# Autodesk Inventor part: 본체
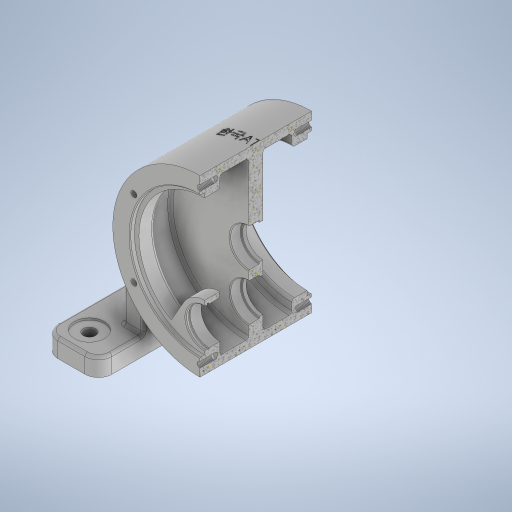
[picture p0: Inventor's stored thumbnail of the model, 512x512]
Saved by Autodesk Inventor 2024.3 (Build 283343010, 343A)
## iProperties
Created: 2025-12
Part Number: 본체
Material: 일반
Document SubType Name: Modeling
Designer: PC2-15
Density: 1 g/cm^3
Appearance: 기본값
Author: PC2-15
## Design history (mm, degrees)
sketch "스케치2"
  geometry: L1 (-135, 100)-(-75, 100); L2 (-75, 100)-(-75, -100); L3 (-75, -100)-(-135, -100); L4 (-135, -100)-(-135, 100); L5 (75, 100)-(135, 100); L6 (135, 100)-(135, -100); L7 (135, -100)-(75, -100); L8 (75, -100)-(75, 100); 2 further points
  constraints: 16 end point, 4 parallel, 2 equal length, 2 horizontal, 2 perpendicular, 1 horizontal alignment, 1 midpoint, 1 point on line
  dimensions: "d4" = 270 distance between parallel lines of L6 L4; "d5" = 135 distance from line of L4 point (0, 0) (= 0.5 x d4); "d6" = 60 distance of L5.start L5.end; "d7" = 200 distance of L5.end L6.end
extrude "돌출2" new body sketch "스케치2" distance "d8" = 20; taper "d9" = 0 deg
sketch "스케치3"
  geometry: L1 (-135, 0)-(-75, 0) reference; C1 r 97 at (0, 120); 1 further point
  constraints: 1 centre point, 1 vertical alignment
  dimensions: "d10" = 120 distance from line of L1 C1.centre; "d11" = 194 diameter of C1
extrude "돌출3" join sketch "스케치3" stored distance "d12" = 124; taper "d13" = 0 deg
sketch "스케치4"
  geometry: L1 (75, 20)-(135, 20) reference; L2 (-135, 20)-(-75, 20) reference; L3 (97, 20)-(97, 120); L4 (-97, 20)-(-97, 120); L5 (97, 120)-(75, 120); L6 (75, 120)-(75, 20); L7 (97, 20)-(75, 20); L8 (-97, 20)-(-75, 20); L9 (-75, 0)-(-75, 20) reference; L10 (-75, 20)-(-75, 120); L11 (-75, 120)-(-97, 120); A1 r 97 centre (0, 120) between (97, 120) and (-97, 120) reference; 2 further points
  constraints: 16 end point, 3 perpendicular, 3 vertical, 2 point on circle, 2 point on line, 2 tangent, 1 collinear, 1 horizontal
extrude "돌출4" join sketch "스케치4" stored distance "d14" = 100; taper "d15" = 0 deg
sketch "스케치5"
  geometry: L1 (75, 58.486)-(75, 20) reference; L2 (75, 8)-(3.735, 49.145); L3 (75, 0)-(135, 0) reference; L4 (75, 0)-(75, 20) reference; 1 further point
  constraints: 2 end point, 1 point on line
  dimensions: "d16" = 8 distance of L3.start L2.start; "d17" = 60 deg angle of L1 L2
feature "리브1" sketch "스케치5" dims "d18" = 1, "d19" = 12, "d20" = 0, "d21" = 0, "d22" = 1, "d23" = 1
sketch "스케치6"
  geometry: L1 (-62, 198)-(-57, 198); L2 (-57, 198)-(-57, 193); L3 (-57, 193)-(-40, 193); L4 (-40, 193)-(-40, 207); L5 (-40, 207)-(-8, 207); L6 (-8, 207)-(-8, 120); L7 (-8, 120)-(-62, 120); L8 (-62, 120)-(-62, 198); L9 (-62, 217)-(-62, 23) reference; L10 (62, 23)-(62, 217) reference; 3 further points
  constraints: 16 end point, 7 perpendicular, 3 midpoint, 1 horizontal
  dimensions: "d24" = 5 distance from line of L8 point (-57, 195.5); "d25" = 22 distance between parallel lines of L4 L8; "d26" = 32 distance from line of L6 point (-40, 200); "d27" = 156 diameter of L1 L7; "d28" = 146 diameter of L3 L7; "d29" = 174 diameter of L5 L7
revolve "회전1" sketch "스케치6" stored, may be unused: angle "d30" = 90 deg
sketch "스케치7"
  geometry: C1 r 87 at (0, 0) reference; 2 further points
  constraints: 1 coincident
hole "구멍1" sketch "스케치7" at (0, 0) diameter "d31" = 38; stored, may be unused: countersink angle "d35" = 90 deg, drill point angle "d37" = 118 deg; dims "d32" = 6, "d33" = 42, "d34" = 12, "d36" = 9
sketch "스케치8"
  geometry: L1 (-37.148, -62.842)-(-23.383, -39); L2 (23.383, -39)-(37.148, -62.842); L3 (0, -52.5)-(0, 0); A1 r 27 centre (0, -52.5) between (23.383, -39) and (-23.383, -39); A2 r 73 centre (0, 0) between (37.148, -62.842) and (-37.148, -62.842) reference; 1 further point
  constraints: 6 end point, 4 point on circle, 2 tangent, 1 centre point, 1 vertical, 1 vertical alignment
  dimensions: "d38" = 60 deg angle of L1 L2; "d39" = 30 deg angle of L3 L1; "d40" = 52.5 distance of L3.start L3.end; "d41" = 27 radius of A1
extrude "돌출5" join sketch "스케치8" distance "d42" = 17; taper "d43" = 0 deg
sketch "스케치9"
  geometry: L1 (-57, 88.5)-(-53.95, 88.5); L2 (-53.95, 88.5)-(-53.95, 89.75); L3 (-53.95, 89.75)-(-52, 89.75); L4 (-52, 89.75)-(-52, 88.5); L5 (-52, 88.5)-(-40, 88.5); L6 (-40, 88.5)-(-40, 67.5); L7 (-40, 67.5)-(-57, 67.5); L8 (-57, 67.5)-(-57, 88.5); L9 (-57, 94.5)-(-57, 81) reference; L10 (-57, 81)-(-57, 57.158) reference; L11 (-57, 42)-(-57, 198) reference; L12 (-57, 57.158)-(-57, 57.158) reference; L13 (-57, 57.158)-(-57, 81) reference; L14 (-57, 81)-(-57, 81) reference; L15 (-57, 81)-(-57, 57.158) reference; L16 (-50, 58.486)-(-6, 58.486) reference; L17 (-57, 81)-(-57, 81) reference; L18 (-57, 81)-(-40, 81) reference; L19 (-40, 81)-(-40, 81) reference; L20 (-57, 81)-(-40, 81) reference; L21 (-40, 57.158)-(-40, 57.158) reference; L22 (-40, 57.158)-(-40, 81) reference; L23 (-40, 81)-(-40, 81) reference; L24 (-40, 81)-(-40, 57.158) reference; L25 (-40, 33)-(-40, 207) reference; L26 (4, 99)-(-8, 99) reference; L27 (-8, 99)-(-8, 141) reference; L28 (4, 141)-(4, 99) reference; 2 further points
  constraints: 16 end point, 6 perpendicular, 4 point on line, 1 horizontal, 1 midpoint
  dimensions: "d44" = 44.5 diameter of L3 L7; "d45" = 1.95 distance between parallel lines of L2 L4; "d46" = 12 distance between parallel lines of L6 L4; "d47" = 42 diameter of L1 L7; "d108" = 52.5 distance from line of point (-8, 120) L7
revolve "회전2" sketch "스케치9" stored, may be unused: angle "d48" = 90 deg
sketch "스케치10"
  geometry: C1 r 21 at (0, -52.5) reference; 2 further points
  constraints: 1 coincident
hole "구멍2" sketch "스케치10" at (0, -52.5) diameter "d49" = 38; stored, may be unused: countersink angle "d53" = 90 deg, drill point angle "d55" = 118 deg; dims "d50" = 6, "d51" = 42, "d52" = 12, "d54" = 8
sketch "스케치11" dims "d56" = 170
  geometry: C1 r 97 at (0, 0) reference; 3 further points
  constraints: 2 vertical alignment, 3 other
hole "구멍3" sketch "스케치11" at (0, 85) diameter "d57" = 6.647; stored, may be unused: countersink angle "d61" = 90 deg, drill point angle "d63" = 118 deg; dims "d58" = 16, "d59" = 4, "d60" = 2, "d62" = 18
sketch "스케치12"
  geometry: L1 (-110, 75)-(110, 75); L2 (110, 75)-(110, -75); L3 (110, -75)-(-110, -75); L4 (-110, -75)-(-110, 75); 7 further points
  constraints: 8 end point, 4 coincident, 2 midpoint, 2 parallel, 1 horizontal, 1 horizontal alignment, 1 perpendicular, 1 vertical alignment
  dimensions: "d67" = 150 distance of L1.end L2.end; "d68" = 220 distance of L2.end L3.end
hole "구멍4" sketch "스케치12" at (-110, 75), (110, 75), (110, -75), (-110, -75) diameter "d69" = 13.5; stored, may be unused: countersink angle "d73" = 90 deg, drill point angle "d75" = 118 deg; dims "d70" = 16, "d71" = 33, "d72" = 2, "d74" = 18
fillet "모깎기1" dims "d76" = 0.6
fillet "모깎기2" dims "d77" = 3
chamfer "모따기1" distance "d78" = 1; stored, may be unused: second distance "d79" = 2, angle "d80" = 45 deg
chamfer "모따기2" distance "d81" = 1; stored, may be unused: second distance "d82" = 2, angle "d83" = 45 deg
chamfer "모따기5" distance "d90" = 1; stored, may be unused: second distance "d91" = 2, angle "d92" = 45 deg
chamfer "모따기6" distance "d93" = 1; stored, may be unused: second distance "d94" = 2, angle "d95" = 45 deg
fillet "모깎기3" dims "d96" = 3
fillet "모깎기4" dims "d97" = 3
fillet "모깎기5" dims "d98" = 15
fillet "모깎기6" dims "d99" = 3
fillet "모깎기7" dims "d100" = 3
fillet "모깎기8" dims "d101" = 3
fillet "모깎기9" dims "d102" = 3
node "작업 평면1"
sketch "스케치13"
  geometry: L1 (-38, 23)-(38, 23); L2 (38, 23)-(38, -23); L3 (38, -23)-(-38, -23); L4 (-38, -23)-(-38, 23); L5 (0, 23)-(0, -23); L6 (-38, 0)-(38, 0); 3 further points
  constraints: 6 midpoint, 4 end point, 1 coincident, 1 vertical alignment, 2 other
  dimensions: "d104" = 76 distance of L1.start L1.end; "d105" = 46 distance of L1.end L2.end
feature "엠보싱1" sketch "스케치13" dims "d106" = 0.5, "d107" = 0
chamfer "모따기7" distance "d109" = 1; stored, may be unused: second distance "d110" = 2, angle "d111" = 45 deg
fillet "모깎기10" dims "d112" = 3
node "솔리드2"
mirror "미러1"
mirror "미러2"
pattern_circular "원형 패턴1" dims angle "d65" = 360 deg
mirror "미러3"
node "투영된 루프1"
node "투영된 루프2"
node "투영된 루프3"
node "투영된 루프4"
feature "A9D066F2-1C7D-4E18-AEED-F7BC21143FA4" dims "d31" = 38, "d32" = 6, "d33" = 42, "d34" = 12, "d35" = 90 deg, "d36" = 9, "d37" = 118 deg
other parameters: "d103" = 243
